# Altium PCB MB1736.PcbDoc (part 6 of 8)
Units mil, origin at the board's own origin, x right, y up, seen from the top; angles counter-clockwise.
Board outline 5905.51 x 3779.53 mil, 6 copper layers (Top Layer, L2_GND, L3_SIG, L4_VCC, L5_GND, Bottom Layer), stack 117.811 mil thick; 481 components, 387 nets, 1904 pads, 1200 vias.
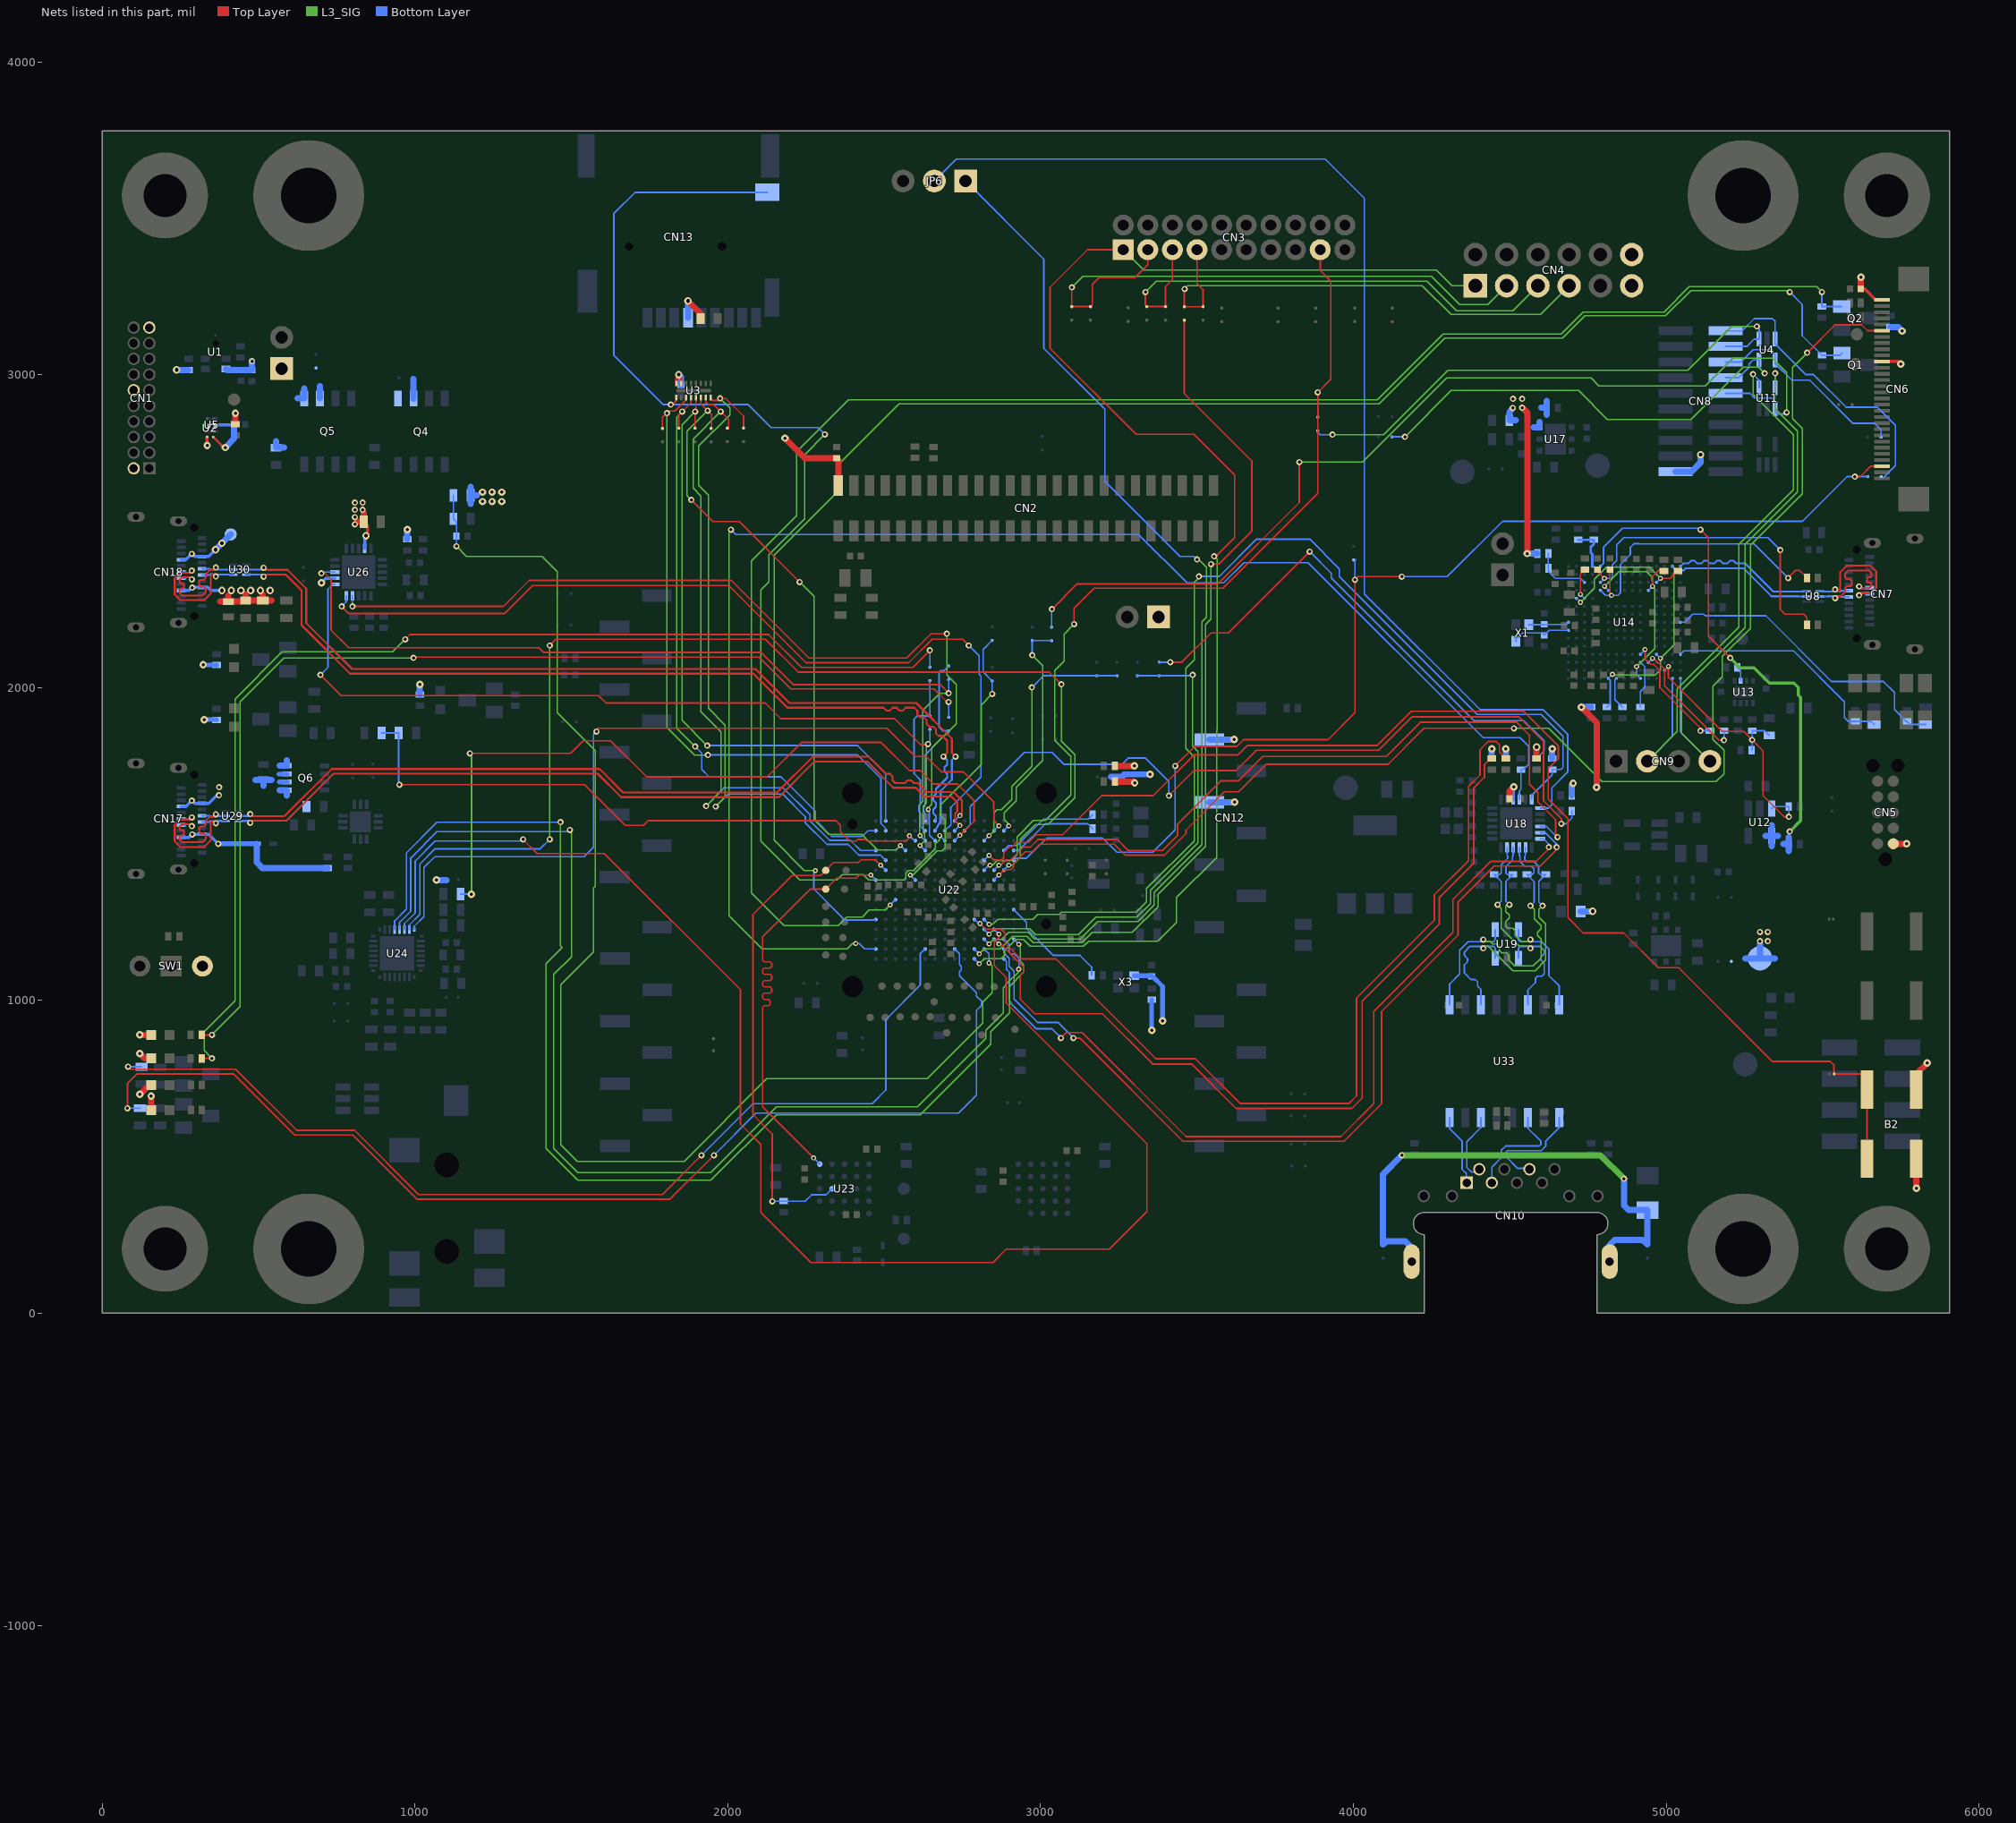
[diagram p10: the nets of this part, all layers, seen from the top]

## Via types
v1: diameter 20, hole 10, Top Layer to Bottom Layer, tented both sides, 518 vias
v2: diameter 16, hole 8, Top Layer to Bottom Layer, tented both sides, 311 vias
v3: diameter 24, hole 10, Top Layer to Bottom Layer, tented both sides, 301 vias
v4: diameter 24, hole 12, Top Layer to Bottom Layer, tented both sides, 61 vias
v5: diameter 23.62, hole 11.81, Top Layer to Bottom Layer, 9 vias

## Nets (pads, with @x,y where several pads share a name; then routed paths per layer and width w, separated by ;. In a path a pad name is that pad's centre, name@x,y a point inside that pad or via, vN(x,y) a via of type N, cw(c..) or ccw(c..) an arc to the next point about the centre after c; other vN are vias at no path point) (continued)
OCTOSPI_IO7: TP42.1 U22.G15 U23.E1 | length 1427
  Top Layer w5: 2252.5,1345.22 2111.09,1203.81 2111.09,1128.52 2116.09,1123.52 2135,1123.52 2140,1118.52 2140,1108.52 2135,1103.52 2116.09,1103.52 2111.09,1098.52 2111.09,1088.52 2116.09,1083.52 2135,1083.52 2140,1078.52 2140,1068.52 2135,1063.52 2116.09,1063.52 2111.09,1058.52 2111.09,1048.52 2116.09,1043.52 2135,1043.52 2140,1038.52 2140,1028.52 2135,1023.52 2116.09,1023.52 2111.09,1018.52 2111.09,1008.52 2116.09,1003.52 2130,1003.52 2135,998.52 2135,988.52 2130,983.52 2116.09,983.52 2111.09,978.52 2111.09,659.61 v2(2274.1,496.6) ; TP42.1@2312.76,1355.91 2347.76,1390.91 2409.69,1390.91 2419.76,1400.98 v2(2457.18,1400.98)
  Top Layer w5.22: 2252.5,1345.22 2263.19,1355.91 TP42.1@2312.76,1355.91
  Bottom Layer w5: v2(2274.1,496.6) U23.E1@2293.78,476.93 ; v2(2457.18,1400.98) U22.G15@2472.94,1385.25
OCTOSPI_NCS: R118.1 TP32.1 U22.F14 U23.C2 | length 1661.3
  Top Layer w5: v1(2141.81,358.19) 2141.81,573.18 2080.1,634.9 2080.1,1275.09 2205,1400 2296.85,1400 TP32.1@2312.76,1415.91 2337.76,1440.91 2417.25,1440.91 2426.34,1450 2471.14,1450 v2(2488.67,1432.47)
  Bottom Layer w5: v1(2141.81,358.19) 2177.32,358.19 R118.1@2177.76,358.62 2178.2,358.19 2247.19,358.19 ; v2(2488.67,1432.47) U22.F14@2504.4,1416.74
  Bottom Layer w5.22: 2247.19,358.19 2268,378.99 2313.96,378.99 U23.C2@2333.15,398.19
PA2: R92.1 U18.12 U22.L4 | length 3437.5
  L3_SIG w4: v2(2835.11,1243.5) 2846.81,1243.5 2863.3,1260 2975.01,1260 2990.01,1275 3060,1275 3067.01,1282 3306.07,1282 3339,1314.93 3339,1358 3491.5,1510.5 3491.5,1778.5 3464,1806 3464,2062 3491.5,2089.5 3491.5,2336.5 3506,2351 v1(3506,2356)
  Bottom Layer w4: U22.L4@2819.37,1259.25 v2(2835.11,1243.5)
  Bottom Layer w5: v1(3506,2356) 3571.01,2356 3689.99,2474.99 3860.01,2474.99 3955,2380 3955,2355 4395,1915 4600,1915 4670,1845 4670,1745 4663.39,1738.39 R92.1@4635.75,1738.4 4635.75,1722.05 4569.96,1656.25 4569.96,1648 U18.12@4569.99,1642.89
PA3: U22.N1 U24.28 | length 3898.2
  L3_SIG w4: v1(1465,1570) 1465,1175 1470,1170 1418.15,1118.15 1418.15,526.85 1520.01,424.99 1945,424.99 2155,635 2615,635 2840,860 2840,900 2900,960 2900,1045 2945,1090 2945,1115 2935,1125 2935,1174.59 v2(2930.3,1179.3)
  Bottom Layer w4: U22.N1@2913.89,1196.27 2930.3,1179.84 v2(2930.3,1179.3)
  Bottom Layer w5: U24.28@934.25,1226.57 934.25,1254.25 972,1292 972,1472 1070,1570 v1(1465,1570)
PA4: U22.M3 U24.30 | length 4726.4
  Top Layer w5: v1(1345,1515) 1390,1470 1605,1470 2040,1035 2040,605 2105,540 2105,322.49 2265,162.49 2847.5,162.49 2890,204.99 3220,204.99 3340,324.99 3340,542 2889.99,992.01 2889.99,1073.64 2852.11,1111.51 2852.11,1155.02 ; 2852.12,1155.03 2852.12,1186.51 2866.61,1201 v2(2866.61,1212.01)
  Bottom Layer w4: U22.M3@2850.87,1227.75 v2(2866.61,1212.01)
  Bottom Layer w5: U24.30@965.75,1226.57 965.75,1245.75 1000,1280 1000,1446 1064,1510 1340,1510 v1(1345,1515)
PA5: U22.N2 U24.29 | length 3812.3
  L3_SIG w4: v1(1495,1545) 1500,1540 1500,1140 1443.15,1083.15 1443.15,526.84 1520,449.99 1945,449.99 2155,660 2606.05,660 2825,878.94 2825,905 2880,960 2880,1040 2888,1048 2888,1049.98 2930,1091.98 v2(2930,1100)
  Bottom Layer w4: U22.N2@2882.39,1196.27 2891.31,1187.34 ; 2891.31,1187.32 2899.31,1179.32 2899.31,1154.8 2904.11,1150 2915,1150 2930,1135 v2(2930,1100)
  Bottom Layer w5: U24.29@950,1226.57 950,1250 986,1286 986,1456 1070,1540 1490,1540 v1(1495,1545)
PA7: SB20.2 SB47.2 U22.M4 | length 1573.9
  L3_SIG w4: v2(2835.11,1212.01) 2853.09,1230 2860.32,1230 2860.81,1229.5 2965.49,1229.5 2984,1211 3120.99,1211 3176,1266 3307.05,1266 3351,1309.95 3351,1352 3503.5,1504.5 3503.5,1796.5 3486,1814 v1(3486,2041)
  Bottom Layer w5: U22.M4@2819.38,1227.75 v2(2835.11,1212.01) ; SB47.2@3309.16,2038.31 3483.31,2038.31 v1(3486,2041)
PA15: SB53.2 SB72.2 U22.G11 | length 932.3
  L3_SIG w4: v2(2583.16,1400.98) 2590.98,1400.98 2668.91,1478.91 2684.76,1478.91 2694.76,1488.91 2694.76,1576.91 2678.76,1592.91 2678.76,1623.75 2810,1755 2810,1945 v1(2845,1980)
  Bottom Layer w5: v2(2583.16,1400.98) U22.G11@2598.88,1385.25 ; v1(2845,1980) SB53.2@2845,2021.37 2816,2050.38 2816,2122.38 SB72.2@2845,2151.37
PB0: U18.17 U22.P2 | length 2802.3
  Top Layer w5: v1(3105,880) 3125,880 3455,550 3970,550 4090,670 4090,965 4335,1210 4335,1315 4450,1430 4597.2,1430 4650,1482.8 v1(4650,1490)
  Bottom Layer w5: U22.P2@2882.39,1164.78 2882.38,1152.6 2899.5,1135.49 2899.5,1109.12 2915,1093.62 2915,1005 2990,930 3055,930 v1(3105,880) ; U18.17@4597.55,1536.59 4601.99,1536.58 4613.43,1536.57 4650,1500 v1(4650,1490)
PB1: U18.18 U22.R2 | length 2728.1
  Top Layer w5: v1(3065,880) 3082.5,897.5 3132.5,897.5 3465,565 3960,565 4065,670 4065,965 4318.3,1218.3 4318.3,1323.3 4440,1445 4585,1445 4625,1485 v1(4625,1490)
  Bottom Layer w5: U22.R2@2882.39,1133.28 2890.5,1125.16 2890.5,1099.5 2900,1090 2900,998.77 2905,993.77 2905,990 2985,910 3035,910 v1(3065,880) ; U18.18@4597.55,1516.9 4608.11,1516.89 4625,1500 v1(4625,1490)
PB2: JP6.1 U22.N4 | length 3351.4
  L3_SIG w4: v2(2835.12,1180.51) 2849.6,1195 2875,1195 2897.51,1217.5 2960.51,1217.5 2981.02,1197 3127,1197 3183.01,1253 3311.02,1253 3363,1304.98 3363,1346 3515.5,1498.5 3515.5,2210.5 3530,2225 3530,2385.94 3505.95,2410 v1(3500,2410)
  Bottom Layer w4: U22.N4@2819.38,1196.25 v2(2835.12,1180.51)
  Bottom Layer w5: JP6.1@2760,3620 3010,3370 3010,3085 3205,2890 3205,2660.5 3445.5,2420 3490,2420 v1(3500,2410)
PB3: SB31.2 SB68.2 U22.C4 | length 849.4
  L3_SIG w4: v2(2835.11,1526.95) 2850,1541.84 2850,1600 2860,1610 2875,1610 2908,1643 2908,1684.98 2972,1748.98 v1(2972,2001)
  Bottom Layer w4: U22.C4@2819.4,1511.24 v2(2835.11,1526.95)
  Bottom Layer w5: v1(2972,2001) 3009.31,2038.31 SB31.2@3179.16,2038.31 SB68.2@3244.16,2038.31
PB5: U22.B3 U24.32 | length 2633.7
  Top Layer w4: 2850,1612.12 2850,1575.09 v2(2866.62,1558.47)
  Top Layer w5: v1(1580,1860) 1580,1865 1585,1870 2508.77,1870 2598.77,1780 2633.65,1780 2682.65,1731 2753,1731 2850,1634 2850,1612.12
  Bottom Layer w4: U22.B3@2850.9,1542.73 v2(2866.62,1558.47)
  Bottom Layer w5: U24.32@997.24,1226.57 997.24,1237.24 1028,1268 1028,1425 1063,1460 1540,1460 1570,1490 1570,1850 v1(1580,1860)
PB10: R99.1 U18.10 U22.P15 | length 4841
  L3_SIG w4: v1(2010,2505) 2003.49,2498.49 2003.49,1271.5 2110,1165 2381.98,1165 2398.99,1182 v2(2409,1182)
  Bottom Layer w5: v1(2010,2505) 2025,2490 3313.01,2490 3468,2335 3585.01,2335 3650,2400 3855,2400 4415,1840 4532.58,1840 4560,1812.58 4560,1755 4543.38,1738.38 R99.1@4535.75,1738.4 4535.75,1675.35 4530.59,1670.19 U18.10@4530.59,1642.89 ; v2(2409,1182) 2419.78,1182 2437.01,1164.76 U22.P15@2472.94,1164.78
PC4: R47.1 U22.L5 | length 2894.1
  Top Layer w5: v2(2806.06,1245.94) 2824.01,1228 2873,1228 2886,1215 2886,1183 2936,1133 3049,1133 3368,814 3494,814 3637,671 3986,671 4010,695 4010,1008 4259,1257 4259,1338 4368,1447 4368,1684 4405,1721 4405,1802 4431,1828 4456,1828 4467,1817 4467,1794.4 R47.1@4487.56,1773.83
  Bottom Layer w4: U22.L5@2787.88,1259.25 2801.18,1245.94 v2(2806.06,1245.94)
PC5: R46.1 U22.N3 | length 2752.7
  Top Layer w5: v2(2866.62,1180.5) 2872.5,1180.5 2945,1108 2945,1090 2935,1080 2935,1004 2981.51,957.5 3197.51,957.5 3358,797 3483,797 3625,655 3995,655 4028,688 4028,998 4275,1245 4275,1330 4385,1440 4385,1680 4419,1714 4419,1754 4434,1769 4434,1773.82 R46.1@4442.56,1773.83
  Bottom Layer w4: U22.N3@2850.87,1196.25 v2(2866.62,1180.5)
PC8: SB13.2 U3.7 U22.D15 | length 2156.3
  Top Layer w5: U3.7@1929.36,2927.35 1929.36,2913.64 1938,2905 1955,2905 v1(1977,2883) 2002,2858 2002,2826.62
  L3_SIG w4: v1(1930,1622) 1978,1670 1978,1859 1914,1923 1914,2613 1889,2638 1889,2795 v1(1977,2883)
  Bottom Layer w5: v1(1930,1622) 1988,1680 2176,1680 2176.11,1680.11 2262.33,1593.9 2262.33,1574.67 2325,1512 2392,1512 2424.28,1479.72 U22.D15@2472.94,1479.74
PC9: SB15.2 U3.8 U22.E14 | length 2239.5
  Top Layer w5: U3.8@1945.12,2927.36 1945.12,2924.88 1952,2918 1968.01,2918 v1(1975,2925) 1993.01,2925 2050,2868 SB15.2@2050,2830
  L3_SIG w4: v1(1961,1620) 1991,1650 1991,1881 1938,1934 1938,2616 1907,2647 1907,2773 2006,2872 2006,2894 v1(1975,2925)
  Bottom Layer w5: v1(1961,1620) 2001,1660 2175.01,1660 2247.33,1587.67 2247.33,1568.89 ; 2247.32,1568.88 2317.19,1499 2384,1499 2418.28,1464.72 2487.92,1464.72 2494.82,1457.82 ; 2494.84,1457.82 U22.E14@2504.44,1448.24
PC10: SB10.2 U3.3 U22.B14 | length 2071.5
  Top Layer w4: SB10.2@1791,2829 1791,2864 v1(1805,2878) 1812,2885 1831,2885 1866.38,2920.38 U3.3@1866.38,2927.36
  L3_SIG w4: v1(1805,2878) 1805,1873 1893,1785 v1(1936,1785)
  Bottom Layer w5: v1(1936,1785) 2415,1785 2489.41,1710.59 2489.41,1565.59 2504.43,1550.58 U22.B14@2504.44,1542.73
PC11: SB3.2 U3.4 U22.B15 | length 1967.9
  Top Layer w5: SB3.2@1843,2829.62 1843,2872 v1(1854,2883) 1882.13,2911.13 U3.4@1882.13,2927.34
  L3_SIG w4: v1(1854,2883) 1836,2865 1836,1871 v1(1895,1812)
  Bottom Layer w5: v1(1895,1812) 1916,1791 1916,1739 1940,1715 2170,1715 2280,1605 2280,1577 2332,1525 2430,1525 2447.71,1542.72 U22.B15@2472.94,1542.73
PC12: SB11.2 U3.6 U22.D12 | length 2005.5
  Top Layer w4: v1(1935,2886) 1948,2873 SB11.2@1948,2833
  Top Layer w5: v1(1883,2600) 1952,2531 2036,2531 v1(2229,2338) ; U3.6@1913.62,2927.35 1913.62,2907.38 v1(1935,2886)
  L3_SIG w4: v1(1883,2600) 1869,2614 1869,2820 v1(1935,2886) ; v1(2229,2338) 2275,2292 2275,1578.95 2322.95,1531 2428.41,1531 2448.95,1510.45 2449.54,1510.45 2478.54,1481.45 2537.67,1481.45 v2(2551.67,1495.45)
  Bottom Layer w4: v2(2551.67,1495.45) U22.D12@2567.43,1479.74
PC13: B2.3 B2.4 U7.1 U22.E4 | length 4133.3
  Top Layer w5: v2(2835.11,1463.97) 2850.38,1448.69 2873.7,1448.69 2882,1457 2882,1473 2901,1492 2909.12,1492 2922.54,1505.42 2960.86,1505.42 2985.44,1530 3070,1530 3195,1655 3360,1655 3490.01,1785 3630.01,1785 3660,1815 4075,1815 4185,1925 4544.39,1925 4655,1814.39 4655,1813.33 4655.25,1813.08 4655.25,1773.5 4623,1741.25 4623,1644.58 4680,1587.58 4680,1587.5 4686,1581.5 4686,1265 4735,1216 4864,1216 4975,1105 5040,1105 5340,805 5525,805 5536.65,793.34 U7.1@5536.66,765 5630,765 5642.52,752.48 B2.4@5642.52,494.54
  Bottom Layer w4: U22.E4@2819.4,1448.24 v2(2835.11,1463.97)
PC14: R112.2 U22.D2 | length 331.4
  Bottom Layer w5: U22.D2@2882.39,1479.74 2898.11,1495.45 2924.46,1495.45 2939.64,1510.64 2939.64,1510.85 3008.63,1579.84 3152.19,1579.84 R112.2@3166.3,1593.93
PC15: R111.2 U22.D1 | length 294.2
  Bottom Layer w5: U22.D1@2913.89,1479.74 2929.72,1479.72 3014.85,1564.84 3150.69,1564.84 R111.2@3166.27,1549.26
PD2: SB17.2 U3.5 U22.A14 | length 1976.8
  Top Layer w5: SB17.2@1895,2829.62 v1(1895,2883) 1895,2891 1897.87,2893.87 U3.5@1897.87,2927.35
  L3_SIG w4: v1(1895,2883) 1852.84,2840.84 1852.84,1896.16 v1(1934,1815)
  Bottom Layer w5: v1(1934,1815) 2415,1815 2504.43,1725.57 U22.A14@2504.44,1574.23
PD4: R70.1 R113.2 U22.C11 | length 1989.4
  Top Layer w5: v1(950,1690) 1541.65,1690 1671.65,1560 1730,1560 1745,1575 2345,1575 2360,1560 2360,1540 2390,1510 2410,1510 2415,1515 2440,1515 2445,1510 2570,1510 2580.66,1520.66 v2(2580.66,1526.57)
  Bottom Layer w4: v2(2580.66,1526.57) 2596,1511.23 U22.C11@2598.93,1511.24
  Bottom Layer w5: R70.1@892.56,1855 R113.2@947.44,1855 947.44,1692.56 v1(950,1690)
PD7: R89.1 U22.B6 | length 2577.6
  Top Layer w5: v1(3410,1655) 3490,1735 3625,1735 3690,1800 4081.22,1800 4188.22,1907 4529,1907 4608.25,1827.75 4608.25,1749.91 4608,1749.66 4608,1638.35 4665,1581.35 v1(4665,1565)
  Bottom Layer w5: U22.B6@2756.39,1542.73 2775,1561.34 2775,1620 2948.18,1793.17 3036.83,1793.17 3075.01,1755 3260,1755 3280,1775 3335,1775 3410,1700 v1(3410,1655) ; v1(4665,1565) 4680,1565 4698.47,1583.47 4698.47,1596 R89.1@4698.49,1606.09
PE2: SB49.2 SB73.2 U22.B2 | length 747.1
  L3_SIG w4: v2(2898.11,1558.45) 2898.11,1564.88 2884,1578.99 2884,1599.99 2922,1637.99 2922,1681.99 3007,1766.99 3007,2070 v1(2973,2104)
  Bottom Layer w4: U22.B2@2882.39,1542.73 v2(2898.11,1558.45)
  Bottom Layer w5: v1(2973,2104) SB49.2@2973,2150.38 SB73.2@3035,2150.38
PE5: CN3.9 SB76.2 U22.F4 | length 2875.2
  Top Layer w5: v1(3106.81,2203.18) 3106.81,2253.81 3171,2318 3583.01,2318 3886,2621 v1(3886,2944) 3928,2986 3928,3300 3893.96,3334.04 CN3.9@3893.96,3400.25
  L3_SIG w4: v2(2838,1432.47) 2846.81,1432.47 2860.81,1446.47 2904.47,1446.47 2925,1467 2925,1523 2977,1575 3015,1575 3097,1657 3097,1780 3045,1832 3045,2055 3075,2085 3075,2171.38 v1(3106.81,2203.18)
  Bottom Layer w4: U22.F4@2819.4,1416.75 2835.11,1432.47 v2(2838,1432.47)
  Bottom Layer w5: SB76.2@3886,2864.8 v1(3886,2944)
PE6: CN6.3 SB51.1 SB77.2 U22.E1 | length 3811.7
  Top Layer w5: v1(3430,1750) 3492.5,1812.5 3627.5,1812.5 3649,1834 3919,1834 4005,1920 v1(4005,2345) 4015,2355 v1(4155,2355) ; v1(5603,2675) 5621.32,2675 5654.5,2708.18 CN6.3@5690,2708.18
  Bottom Layer w5: U22.E1@2913.89,1448.24 2920.63,1455 2955,1455 3020,1520 3197.46,1520 3243.45,1474 3358.33,1474 3430,1545.67 v1(3430,1750) ; v1(4005,2345) 4005,2406 4008,2409 ; v1(4155,2355) 4300,2355 4476.9,2531.9 5435.9,2531.9 5579,2675 v1(5603,2675) SB77.2@5644.69,2675
PE9: SB7.1 U22.P5 | length 2775.6
  Top Layer w5: SB7.1@3459.31,3174.75 3459.31,2940.68 3675,2725 3675,2500.25 3569.75,2395 v1(3545,2395)
  L3_SIG w4: v2(2803.62,1149.01) 2819.6,1165 2870.91,1165 2910.91,1205 2956.04,1205 2976.04,1185 3131.98,1185 3164.98,1218 3293,1218 3375,1300 3375,1340 3527.5,1492.5 3527.5,2202.5 3545,2220 v1(3545,2395)
  Bottom Layer w5: U22.P5@2787.9,1164.74 v2(2803.62,1149.01)
PE10: CN3.1 CN4.1 U22.R5 | length 4662.1
  Top Layer w5: CN3.1@3264.04,3400.25 3150.26,3400.25 3030,3280 3030,3085 3305,2810 3489.64,2810 3620,2679.64 3620,2480 3560,2420 v1(3555,2420)
  L3_SIG w4: v2(2803.62,1117.52) 2820.09,1134 2874,1134 2885,1145 2885,1160 2920,1195 2945,1195 2967,1173 3136.96,1173 3153.96,1190 3374.06,1190 3434.01,1249.94 3434.01,1329 3562.5,1457.49 3562.5,1863.43 3564,1864.93 3564,2411 v1(3555,2420) ; CN3.1@3264.04,3400.25 3329.3,3335 4265,3335 4315,3285 CN4.1@4390,3285
  Bottom Layer w5: U22.R5@2787.9,1133.25 v2(2803.62,1117.52)
PF5: CN6.25 U22.G3 | length 4452.3
  Top Layer w5: v2(2866.61,1400.98) 2883.6,1417.97 2904.12,1417.97 2912.61,1426.45 2912.61,1437.6 2950.42,1475.42 2973.3,1475.42 2997.88,1500 3235,1500 3270,1465 3396.22,1465 3465,1533.77 3465,1545 3587.5,1667.5 3632.5,1667.5 3720,1755 4110,1755 4225,1870 v1(4513,1870) ; v1(5451.01,3071) 5540,3160 5625,3160 5643.74,3141.25 CN6.25@5690,3141.25
  L3_SIG w4: v1(4513,1870) 4625,1870 4795,1700 5160,1700 5185,1725 5185,1800 5150,1835 5150,2005 5180,2035 5180,2100 5270,2190 5270,2455 5435,2620 5435,2829 5404,2860 5404,3024 v1(5451.01,3071)
  Bottom Layer w4: U22.G3@2850.9,1385.25 v2(2866.61,1400.98)
PF14: C136.2 R135.2 R136.1 U22.P4 | length 4264.8
  L3_SIG w4: v1(1132.28,2452.27) 1164.56,2420 1405,2420 1454,2371 1454,1921 1576,1799 1576,1364.94 1570,1358.94 1570,1155 1466,1051 1466,537.94 1517.95,486 1859.95,486 2123.95,750 2637,750 2815,928 2815,995 2845,1025 2845,1110 v2(2835,1120)
  Bottom Layer w5: R136.1@1122.44,2615 R135.2@1122.44,2540 1132.29,2530.15 1132.29,2485 v1(1132.28,2452.27) ; U22.P4@2819.4,1164.78 2835,1149.17 v2(2835,1120)
PG11: U18.16 U22.F3 | length 2406.6
  Top Layer w5: v2(2866.61,1432.47) 2872.47,1432.47 2889.47,1449.47 2904.12,1449.47 2945.07,1490.42 2967.08,1490.42 2991.66,1515 3245,1515 3280,1480 3390,1480 3437.5,1527.5 3437.5,1562.5 3577.5,1702.5 3632.5,1702.5 3710,1780 4105,1780 4215,1890 4521.01,1890 4563,1848 4563,1691 4590,1664 4590,1635.14 4646.5,1578.64 4646.5,1528.25 v1(4652.38,1522.38)
  Bottom Layer w4: U22.F3@2850.9,1416.75 v2(2866.61,1432.47)
  Bottom Layer w5: U18.16@4597.55,1556.27 4617.05,1556.26 4650.94,1522.38 v1(4652.38,1522.38)
PG12: U22.F2 U24.31 | length 3731.8
  Top Layer w5: v1(1430,2135) 1450,2155 2120,2155 2225,2050 3027.01,2050 v1(3066,2011)
  L3_SIG w4: v1(1430,1515) v1(1430,2135) ; v2(2898.11,1432.47) 2909.47,1432.47 2935,1458 2935,1515 2983,1563 3023,1563 3109,1649 3109,1786 3065,1830 3066,1831 v1(3066,2011)
  Bottom Layer w4: U22.F2@2882.39,1416.75 v2(2898.11,1432.47)
  Bottom Layer w5: U24.31@981.5,1226.57 981.5,1241.5 1015,1275 1015,1436 1064,1485 1400,1485 v1(1430,1515)
PH0: R114.2 U22.K1 | length 363.3
  Bottom Layer w5: U22.K1@2913.87,1290.75 2955,1249.62 2955,1230 3041,1144 3126,1144 3163.16,1106.84 R114.2@3163.18,1080.51
PM0: SB45.1 U22.D10 U26.1 | length 2758.3
  Top Layer w5: v1(697,2041) 763,1975 1586,1975 1610,1951 2119,1951 2169,1901 2533,1901 2615.87,1818.12 2638.13,1818.12 v1(2640,1820)
  L3_SIG w4: v2(2614.66,1495.45) 2628.66,1509.45 2628.66,1532.75 2625,1536.42 2625,1621.15 2635,1631.15 2635,1815 v1(2640,1820)
  Bottom Layer w4: v2(2614.66,1495.45) 2622.56,1487.56 U22.D10@2630.42,1479.74
  Bottom Layer w5: v1(697,2041) 721,2065 721,2316 735.35,2330.34 U26.1@743.36,2330.35 ; v1(2640,1820) 2645.87,1825.86 SB45.1@2645.87,1866.16
PM1: SB43.1 U22.C10 U26.3 | length 2882.2
  Top Layer w5: v1(700,2366) 711,2366 731,2346 731,2184 787.5,2127.5 1395.5,2127.5 1410,2113 2105.42,2113 2208.42,2010 2678.46,2010 v1(2705.87,1982.59)
  L3_SIG w4: v2(2614.66,1526.95) 2612.9,1528.72 2612.9,1626.34 2623,1636.44 2623,1696.75 2622.5,1697.25 2622.5,1927.5 2677.59,1982.59 v1(2705.87,1982.59)
  Bottom Layer w4: v2(2614.66,1526.95) U22.C10@2630.39,1511.23
  Bottom Layer w5: v1(700,2366) 703.71,2369.7 U26.3@743.36,2369.73 ; v1(2705.87,1982.59) SB43.1@2705.87,2026.15
PM2: SB45.2 SB46.2 U22.B10 | length 543.7
  Bottom Layer w5: U22.B10@2630.42,1542.73 2619.08,1554.06 2615,1558.11 2615,1600 2610,1605 2610,1622.75 2615,1627.75 2615,1705.4 2595,1725.4 2595,1900 2604.44,1909.44 2645.87,1909.44 SB46.2@2645.87,2022.22
PM3: SB42.2 SB43.2 U22.A10 | length 594.9
  Bottom Layer w5: U22.A10@2630.42,1574.23 2630.42,1600.5 2625,1605.92 2625,1616.52 2630,1621.52 2630,1785 2695.87,1850.86 2700.87,1850.86 2705.87,1855.86 SB42.2@2705.87,1862.22 ; 2687.79,1862.2 SB42.2@2705.87,1862.22 ; SB43.2@2705.87,2069.44 2690.87,2054.44 2679.45,2054.44 2675,2050 2675,1875 2687.78,1862.22 SB42.2@2705.87,1862.22
PM5: U22.B9 U30.5 | length 2873.6
  Top Layer w6.1: v1(515.24,2383.25) 521.74,2376.75 591.92,2376.75 651.76,2316.91 651.76,2206.45 798.22,2060 2087.66,2060 2196.66,1951 2602.22,1951 2715.99,1837.23 2715.99,1791.67 v1(2727.66,1780)
  Bottom Layer w6.1: U30.5@459.67,2377.5 485.45,2377.5 485.82,2377.12 509.12,2377.12 v1(515.24,2383.25) ; U22.B9@2661.92,1542.73 2680.45,1576 2680.45,1670.44 2715.99,1705.99 2715.99,1768.33 v1(2727.66,1780)
PM6: U22.A9 U30.6 | length 2872.5
  Top Layer w6.1: v1(515.24,2355.25) 521.74,2361.75 585.7,2361.75 636.76,2310.68 636.76,2200.24 792,2045 2081.44,2045 2190.44,1936 2497.6,1936 2506.4,1927.19 2518.4,1927.19 2527.2,1936 2539.2,1936 2548,1927.19 2560,1927.19 2568.8,1936 2596,1936 2606.03,1925.97 2606.03,1913.51 2614.52,1905.02 2626.97,1905.02 2635.45,1896.55 2635.45,1884.09 2643.94,1875.6 2656.39,1875.6 2664.87,1867.12 2664.87,1854.67 2673.36,1846.18 2685.81,1846.18 2700.99,1831 2700.99,1791.66 v1(2689.33,1780)
  Bottom Layer w6.1: U30.6@459.67,2361.75 485.44,2361.75 485.82,2362.12 508.36,2362.12 v1(515.24,2355.25) ; U22.A9@2661.92,1574.23 2665.45,1577.76 2665.45,1589.76 2656.65,1598.57 2656.65,1610.57 2665.45,1619.36 2665.45,1631.36 2656.65,1640.17 2656.65,1652.17 2665.45,1660.97 2665.45,1676.67 2700.99,1712.2 2700.99,1724.2 2692.19,1733 2692.19,1745 2700.99,1753.81 2700.99,1768.34 v1(2689.33,1780)
PM8: U22.C9 U26.19 | length 2823.2
  Top Layer w5: v1(799.44,2260) 1282,2260 1365,2343 2011,2343 2259,2095 2572,2095 2649.5,2172.5 v1(2700,2172.5)
  L3_SIG w4: v2(2640.73,1610.72) 2641.6,1611.59 2641.6,1616.59 2651.76,1626.75 2651.76,1806.91 2730,1885.15 2730,2010 2700,2040 v1(2700,2172.5)
  Bottom Layer w4: v2(2640.73,1610.72) 2640.73,1609.26 2645,1605 2645,1528.1 2654.05,1519.06 U22.C9@2661.9,1511.23
  Bottom Layer w5: v1(799.44,2260) U26.19@799.46,2293.94
PM9: U22.B8 U26.20 | length 2889.8
  Top Layer w5: v1(765,2260) 788,2237 1286,2237 1376,2327 2003,2327 2250,2080 2578,2080 2653,2155 2750,2155 v1(2770,2135)
  Bottom Layer w4: U22.B8@2693.39,1542.72 2712.5,1561.83 2712.5,1582.5
  Bottom Layer w5: v1(765,2260) 779.76,2274.75 U26.20@779.77,2293.94 ; 2712.5,1582.5 2712.5,1617.5 2809,1714 2809,2037 2803,2043 2803,2102 v1(2770,2135)
PM11: U22.B7 U29.6 | length 2603.8
  Top Layer w6.1: v1(472.24,1568.25) 478.74,1574.75 588.76,1574.75 738.95,1724.94 1583.83,1724.94 1658.78,1650 2163.22,1650 2277.22,1764 2444.78,1764 2528.78,1680 2600.78,1680 2628.78,1652 2714.78,1652 2733.05,1633.73 2733.05,1603.66 2726.58,1597.18 2726.58,1574.5 v2(2741.63,1559.45)
  Bottom Layer w6.1: U29.6@435.67,1574.25 466.25,1574.25 v1(472.24,1568.25) ; U22.B7@2724.89,1542.72 v2(2741.63,1559.45)
PM12: U22.A7 U29.5 | length 2605.7
  Top Layer w6.1: v1(472.24,1596.25) 478.74,1589.75 582.54,1589.75 732.78,1740 1590,1740 1665,1665 2157,1665 2271,1779 2451,1779 2505.58,1724.42 2518.03,1724.42 2526.52,1715.93 2526.52,1703.48 2535,1695 2565.4,1695 2574.2,1703.8 2586.2,1703.8 2595,1695 2607,1695 2635,1667 2721,1667 2748.05,1639.94 2748.05,1597.43 2741.63,1591.01 v2(2741.63,1590.94)
  Bottom Layer w6.1: U29.5@435.67,1590 465.98,1590 v1(472.24,1596.25) ; U22.A7@2724.91,1574.23 v2(2741.63,1590.94)
PM13: R131.2 U22.C7 | length 2440
  Top Layer w5: v1(1175,1790) 1497.44,1790 1537.44,1830 1625,1830 1740,1715 2125.01,1715 2235,1825 2490.11,1825 2580.11,1735 2614.99,1735 2657.99,1692 2734,1692 2787.1,1638.9 2787.1,1573.42 v2(2741.63,1527.95)
  L3_SIG w5: v1(1175,1790) 1174.21,1789.21 1180,1783.43 v3(1180,1340)
  Bottom Layer w5: R131.2@1145.12,1340 v3(1180,1340) ; U22.C7@2724.89,1511.22 v2(2741.63,1527.95)
PM14: CN13.10 U3.1 U22.C8 | length 3914.7
  Top Layer w5: v1(1817,2905) 1822,2905 1834.88,2917.88 U3.1@1834.88,2927.35
  L3_SIG w4: v1(2310,2810) 2245,2745 2245,2540 2131,2426 2131,2338 2105,2312 2105,1510 2230,1385 2347.98,1385 2364.98,1402 2433,1402 2450,1385 2562.85,1385 2569.16,1391.31 2569.16,1406.77 2577.36,1414.98 2592.83,1414.98 2663.63,1485.77 2663.63,1501.3 2677.14,1514.81 v2(2677.14,1527.47)
  Bottom Layer w4: v2(2677.14,1527.47) U22.C8@2693.37,1511.24
  Bottom Layer w5: CN13.10@2102,3583.77 1703.78,3583.77 1635,3515 1635,3063 1793,2905 v1(1817,2905) 2065,2905 2138,2832 2288,2832 v1(2310,2810) ; CN13.10@2102.01,3583.78 CN13.10@2126.27,3583.8
PMOD2: CN3.2 CN4.2 SB1.2 SB2.2 | length 1913.3
  Top Layer w5: v1(3100,3280) 3099.31,3279.31 SB1.2@3099.31,3218.37 3159.3,3218.34 3165,3224.05 3165,3289 3187,3311 3301,3311 3342.78,3352.77 CN3.2@3342.78,3400.25
  L3_SIG w4: v1(3100,3280) 3135,3315 4250,3315 4340,3225 4430,3225 CN4.2@4490,3285
PMOD3: CN3.3 CN4.3 SB5.2 SB6.2 | length 1641.6
  Top Layer w5: v1(3335,3265) 3335,3222.66 3339.31,3218.34 3345.99,3218.35 3399.31,3218.35 3399.31,3282.31 3421.52,3304.51 CN3.3@3421.52,3400.25
  L3_SIG w4: v1(3335,3265) 3370,3300 4235,3300 4330,3205 4510,3205 CN4.3@4590,3285
PMOD4: CN3.4 CN4.4 SB7.2 SB8.2 | length 1618
  Top Layer w5: v1(3460,3275) 3459.31,3274.31 SB7.2@3459.31,3218.06 SB8.2@3518.99,3218.03 ; CN3.4@3500.26,3400.25 3500.26,3291.74 3519.31,3272.68 SB8.2@3519.31,3218.37 ; SB8.2@3518.99,3218.03 SB8.2@3519.31,3218.35 ; SB8.2@3519,3218.03 SB8.2@3519.31,3218.34
  L3_SIG w4: v1(3460,3275) 3470,3285 4220,3285 4312,3193 4598,3193 CN4.4@4690,3285
PN7: Q2.2 R65.1 U22.J13 | length 5621.1
  L3_SIG w4: v2(2518.84,1305.17) 2502.68,1289 2451.38,1289 2429.37,1267 2380,1267 2353,1240 2180,1240 2075.49,1344.5 2075.49,2405.49 2220,2550 2220,2755 2385,2920 4077,2920 4287,3130 4663.8,3130 4734.8,3201 4992.98,3201 5073.98,3282 5480.95,3282 v1(5497.95,3265)
  Bottom Layer w4: v2(2518.84,1305.17) U22.J13@2535.93,1322.25
  Bottom Layer w5: v1(5497.95,3265) R65.1@5497.95,3218.91 5498.27,3218.59 Q2.2@5561.37,3218.6
PN12: Q1.2 R64.1 U22.L15 | length 5346.9
  L3_SIG w4: v2(2280,1415.5) 2244.5,1415.5 2148,1512 2148,2423.64 2358,2633.64 2358,2718.62 2547.37,2908 4081.98,2908 4291.98,3118 4668.78,3118 4739.78,3189 4997.96,3189 5078.96,3270 5391,3270 5395,3266 v1(5395,3265)
  Bottom Layer w5: v2(2280,1415.5) 2280,1415 2275,1410 2275,1356.2 2374.08,1257.12 2440.87,1257.12 2441,1257 2470.67,1257 U22.L15@2472.94,1259.27 ; v1(5395,3265) 5435,3225 5435,3125.73 R64.1@5498,3062.73 5555.29,3062.73 Q1.2@5562.19,3069.62
PO1: R171.1 U22.P7 | length 3664.6
  Top Layer w5: v1(80,655.7) 80,735 110,765 420,765 615,570 800,570 1005,364.99 1815,364.99 v1(1955,505)
  Bottom Layer w5: v1(80,655.7) 113,655.7 R171.1@120,655.72 ; v1(1955,505) 2090,640 2738,640 2795,697 2795,968.3 2811.36,984.66 2811.36,997.51 2795,1013.88 2795,1025 2740.63,1079.36 2740.63,1092.51 2745.8,1097.68 2745.8,1109.7 2740.63,1114.88 2740.63,1149.01 U22.P7@2724.9,1164.75
PO5: R170.1 U22.P10 | length 3276.7
  Top Layer w5: v1(81.73,788.26) 90,780 426.22,780 621.22,585 806.22,585 1011.22,379.99 1790,379.99 v1(1915,505)
  Bottom Layer w5: v1(81.73,788.26) R170.1@125,788.28 ; v1(1915,505) 2080,670 2461,670 2505,714 2505,939 2615,1049 2615,1149.35 U22.P10@2630.42,1164.78
RD_N: R100.1 U18.22 U19.6 U33.8 | length 763.4
  L3_SIG w4.1: v1(4499.12,1306) 4491.6,1306 4487.5,1301.9 4487.5,1284.38 4498.3,1273.58 4498.3,1263.58 4487.5,1252.77 4487.5,1237.5 4494.57,1230.42 4509.85,1230.42 4516.92,1223.35 4516.92,1208.08 4536.76,1188.24 4559.86,1188.24 v1(4566.36,1194.74)
  Bottom Layer w5.1: v1(4499.12,1306) 4487.5,1317.61 4487.5,1380.24 R100.1@4510,1402.73 4492.58,1402.74 4487.5,1407.82 4487.5,1427.5 4508.56,1448.56 4508.56,1461.43 4510.91,1463.78 4510.91,1474 U18.22@4510.93,1489.34 ; U19.6@4528.19,1226.01 4528.18,1193.34 4533.28,1188.24 4559.86,1188.24 v1(4566.36,1194.74) 4572.86,1188.24 4601.75,1188.24 4625,1164.99 4625,1080 4657.76,1047.24 U33.8@4657.76,986.02
RD_P: R103.1 U18.23 U19.1 U33.6 | length 765.5
  L3_SIG w4.1: v1(4460.88,1306) 4472.5,1294.38 4472.5,1231.27 4530.54,1173.24 4559.86,1173.24 v1(4566.36,1166.74)
  Bottom Layer w5.1: v1(4460.88,1306) 4472.5,1317.61 4472.5,1380.24 R103.1@4450,1402.73 4467.42,1402.74 4472.5,1407.82 4472.5,1433.72 4493.56,1454.77 4493.56,1461.43 4491.22,1463.77 4491.22,1475 U18.23@4491.25,1489.34 ; U19.1@4528.19,1135.45 4528.18,1168.14 4533.28,1173.24 4559.86,1173.24 v1(4566.36,1166.74) 4572.86,1173.24 4595.53,1173.24 4610,1158.76 4610,1148.76 4600.2,1138.97 4600.2,1128.97 4610,1119.17 4610,1085 4602.93,1077.92 4589.06,1077.92 4581.99,1070.85 4581.99,1056.99 4557.76,1032.75 U33.6@4557.76,986.02
RMII.RMII_CRS_DV: R96.1 SB20.1 | length 1703.2
  Top Layer w5: v1(3414.84,2081.62) 3451.63,2081.62 3545,2175 3600,2175 v1(3860,2435)
  Bottom Layer w5: SB20.1@3379.16,2081.62 v1(3414.84,2081.62) ; v1(3860,2435) 3929,2366 3929,2351 4385,1895 4545,1895 4610,1830 4610,1798.09 4605.25,1793.34 4605.25,1792.67 4593.83,1781.25 4593.16,1781.25 R96.1@4585.75,1773.83
RMII.RMII_MDC: JP6.2 U18.13 | length 3844.2
  Bottom Layer w5: JP6.2@2660,3620 2730,3690 3910,3690 4035,3565 4035,2300 4405,1930 4606.22,1930 4685,1851.22 4685,1730 4634.4,1679.4 4634.4,1625.9 4623.81,1615.31 4618,1615.31 U18.13@4597.55,1615.33
RX_N: CN10.6 U33.9 | length 349.5
  Bottom Layer w5.1: CN10.6@4563,463 4525.67,463 4487.76,500.91 4487.76,514.9 4492.86,520 4600.87,520 4614.76,533.89 4614.76,549.75 4657.76,592.75 U33.9@4657.76,625.78
RX_P: CN10.3 U33.11 | length 351.9
  Bottom Layer w5.1: CN10.3@4442.52,419.69 4442.52,467.5 4472.76,497.75 4472.76,521.11 4486.64,535 4594.65,535 4599.76,540.1 4599.76,550.23 4557.76,592.23 U33.11@4557.76,625.78
SHGND: C158.1 CN10.SH1 CN10.SH2 SB69.1 SB70.1 | length 1658.9
  L3_SIG w20: v1(4155,505) 4790,505 v1(4865,429.99)
  Bottom Layer w20: v1(4155,505) 4095,444.99 SB70.1@4095,219.68 4105.32,229.99 4166.22,229.99 4186.22,209.99 CN10.SH1@4186.22,167.72 ; CN10.SH2@4819.29,167.72 4819.29,219.28 4835,234.99 4924.68,234.99 SB69.1@4940,219.68 C158.1@4940,329.88 4880.12,329.88 4865,344.99 v1(4865,429.99)
STLK_LED: R62.2 R63.2 U14.D15 | length 750.4
  Bottom Layer w5: U14.D15@5045.77,2106.67 5056.58,2117.5 5407.5,2117.5 5570,1955 5570,1905 5582.72,1892.27 R63.2@5605,1892.29 5655.16,1892.27 R62.2@5665,1882.45
STLK_OSC_IN: C95.2 U14.G1 X1.1 | length 191.6
  Bottom Layer w5: X1.1@4519.33,2148.43 4519.33,2153.47 4540.77,2174.91 4602.82,2174.91 C95.2@4610,2167.72 4625.72,2183.44 U14.G1@4687.5,2183.44
STLK_OSC_OUT: C96.1 U14.H1 X1.3 | length 129.9
  Bottom Layer w5: X1.3@4560.67,2201.57 4609.29,2201.58 C96.1@4610,2202.29 4680.75,2202.28 U14.H1@4687.5,2209.03
STLK_SWCLK: CN9.2 U11.4 U14.A14 | length 1833.9
  L3_SIG w4: CN9.2@4940,1765 5035,1860 5035,1996.22 5232.76,2193.98 5232.76,2458.98 5406.89,2633.1 5406.89,2808.1 5277.5,2937.5 v1(5277.5,3002.5)
  Bottom Layer w4: 5020.17,2010.91 U14.A14@5020.18,2029.9
  Bottom Layer w5: CN9.2@4940,1765 5020.17,1845.17 5020.17,2010.91 ; v1(5277.5,3002.5) 5297.17,2982.83 U11.4@5297.17,2959.36
STLK_SWDIO: CN9.4 U11.5 U14.A15 | length 1809.8
  L3_SIG w4: CN9.4@5140,1765 5050,1855 5050,1990 5252.76,2192.75 5252.76,2457.75 5420,2625 5420,2820 5348.35,2891.65 v1(5348.35,3005)
  Bottom Layer w4: 5045.76,2010.91 U14.A15@5045.77,2029.9
  Bottom Layer w5: 5045.76,2010.91 5045.76,2005 5045.75,1859.25 CN9.4@5140,1765 ; U11.5@5348.35,2959.36 v1(5348.35,3005)
STLK_UCPD_CC1_C: C61.1 R53.1 U14.M5 | length 952
  Top Layer w4: C61.1@4820,2377.29 4820,2300 v2(4825,2295)
  Top Layer w5: v1(5390,2350.91) 5414.09,2375 5425.95,2375 5430.55,2370.4 5431.08,2370.4 5442.5,2358.98 5442.5,2358.44 R53.1@5450.04,2350.91
  Bottom Layer w4: U14.M5@4789.86,2311.4 4806.24,2295 v2(4825,2295)
  Bottom Layer w5: v2(4825,2295) 4845.75,2295 4854,2303.25 4854,2394 4885.55,2425.55 4885.55,2448.69 4896.97,2460.11 4913.13,2460.11 4913.25,2460 5280.91,2460 v1(5390,2350.91)
STLK_UCPD_CC2_C: C59.1 R54.1 U14.N5 | length 1050.1
  Top Layer w5: C59.1@4780,2377.29 4780,2372.41 v2(4802.65,2349.75) ; v1(5365,2440) 5365,2250 5380,2235 5440,2235 5450.04,2224.95 R54.1@5450.04,2200.91
  Bottom Layer w5: U14.N5@4789.86,2336.99 v2(4802.65,2349.75) 4824.76,2349.75 4827.37,2352.35 4827.37,2392.35 4842,2407 4842,2457 4865,2480 5325,2480 v1(5365,2440)
STLK_USB_CN_N: CN7.A7 CN7.B7 U8.2 | length 465.2
  Top Layer w6.1: v1(5540.01,2286) 5546.51,2292.5 5558.51,2292.5 5571.77,2305.76 5571.77,2317.98 5578.77,2324.98 5588.77,2324.98 5593.77,2329.98 5593.77,2340.98 5587.77,2346.98 5578.77,2346.98 5571.77,2353.98 5571.77,2363.76 5583.01,2375 5647.76,2375 5656.77,2365.98 5656.77,2356.98 5652.77,2352.98 5645.77,2352.98 5641.77,2348.98 5641.77,2339.98 5645.77,2335.98 5652.77,2335.98 5656.77,2331.98 5656.77,2325.5 5648.61,2317.34 5623.44,2317.34 v1(5616.94,2323.84)
  Bottom Layer w6.1: U8.2@5490.67,2292 5516.45,2292 5516.82,2292.36 5533.64,2292.36 v1(5540.01,2286) 5546.51,2292.5 5557.87,2292.5 5560.21,2290.16 CN7.A7@5584.02,2290.16 ; v1(5616.94,2323.84) 5623.45,2317.33 5635.56,2317.33 5637.92,2319.68 CN7.B7@5650.93,2319.67
STLK_USB_CN_P: CN7.A6 CN7.B6 U8.1 | length 465
  Top Layer w6.1: v1(5540.01,2314) 5546.51,2307.5 5552.28,2307.5 5556.77,2311.98 5556.77,2369.98 5576.78,2390 5653.98,2390 5671.77,2372.2 5671.77,2319.27 5654.83,2302.34 5623.44,2302.34 v1(5616.94,2295.84)
  Bottom Layer w6.1: U8.1@5490.67,2307.74 5516.44,2307.75 5516.82,2307.36 5533.38,2307.36 v1(5540.01,2314) 5546.51,2307.5 5557.87,2307.5 5560.21,2309.84 CN7.A6@5584.02,2309.84 ; v1(5616.94,2295.84) 5623.43,2302.33 5637.68,2302.33 5640.01,2300 CN7.B6@5650.93,2299.99
STLK_USB_N: U8.5 U14.R14 | length 474.6
  Bottom Layer w6.1: U14.R14@5020.15,2388.15 5033,2375.3 5056.3,2375.3 5063,2382 5246.78,2382 5336.41,2292.36 5423.18,2292.36 5423.55,2292 U8.5@5449.33,2292
STLK_USB_P: U8.6 U14.R15 | length 473.7
  Bottom Layer w6.1: U14.R15@5045.77,2388.17 5054.59,2397 5070.2,2397 5079,2405.8 5091,2405.8 5099.8,2397 5111.8,2397 5120.6,2405.8 5132.6,2405.8 5141.4,2397 5153.4,2397 5162.2,2405.8 5174.2,2405.8 5183,2397 5195,2397 5203.8,2405.8 5215.8,2405.8 5224.6,2397 5253,2397 5342.63,2307.36 5423.18,2307.36 5423.56,2307.75 U8.6@5449.33,2307.74
STLK_VCP_RX: R52.1 U14.C10 | length 154.2
  Bottom Layer w5: R52.1@4917.76,1938.62 4917.76,1987.75 4931.98,2001.97 4931.98,2066.92 U14.C10@4917.82,2081.08
STLK_VCP_TX: R56.1 U14.A7 | length 104.4
  Bottom Layer w5: U14.A7@4841.04,2029.9 4835.83,2024.69 4835.83,1961.89 R56.1@4860,1937.72
T_JTDI: R49.1 U14.L3 | length 102.6
  Top Layer w5: v2(4725.91,2298.61) 4725.91,2363.19 R49.1@4740,2377.29
  Bottom Layer w5: v2(4725.91,2298.61) U14.L3@4738.68,2285.81
T_PWR_EN: R66.2 R177.2 U12.4 U13.2 U14.R5 | length 1842.3
  Top Layer w5: v1(5110,2505) 5135,2480 5135,2165 v1(5205,2095)
  L3_SIG w10: v1(5205,2095) 5236,2064 5281,2064 5330,2015 5408,2015 5423,2000 5423,1975.88 5430,1968.88 5430,1575 v1(5395,1540)
  Bottom Layer w5: U14.R5@4789.85,2388.16 4800,2398.31 4800,2450 4860,2510 5105,2510 v1(5110,2505) ; v1(5205,2095) 5227.72,2072.27 R177.2@5227.72,2065 5238.2,2054.51 U13.2@5238.2,2022.09
  Bottom Layer w20: 5317.59,1526.69 U12.4@5337.42,1526.69 ; 5337.42,1493.09 U12.4@5337.42,1526.69 ; 5337.42,1560.31 U12.4@5337.42,1526.69 ; 5357.25,1526.69 U12.4@5337.42,1526.69 ; 5374.23,1500 R66.2@5392.3,1500 ; 5392.29,1478.19 R66.2@5392.3,1500 ; 5392.29,1521.8 R66.2@5392.3,1500
T_PWR_EXT: R86.1 R88.1 U14.R4 | length 141
  Bottom Layer w8: R88.1@4719.18,2472.82 R86.1@4769.18,2472.82 4769.18,2459.84 4759,2449.66 4759,2432.25 4764.27,2426.99 U14.R4@4764.27,2388.17
T_PWR_INT: C4.2 R67.1 R68.2 R75.2 U12.3 U14.B13 | length 921.7
  Top Layer w5: v2(5007.39,2068.27) 5007.39,2032.6 5180,1860 5248.15,1860 v1(5275,1833.15) 5310,1798.15 5310,1655 5377.71,1587.28 v1(5392.29,1587.28)
  Bottom Layer w5: U14.B13@4994.61,2055.5 v2(5007.39,2068.27) ; R67.1@5272.73,1800 5275,1802.26 v1(5275,1833.15) R75.2@5275,1862.29 5315.15,1862.28 C4.2@5330,1847.43 ; U12.3@5337.42,1613.31 5344.11,1620 R68.2@5392.3,1620 v1(5392.29,1587.28)
T_PWR_LED: R59.2 R60.2 U14.H15 | length 973.3
  Bottom Layer w5: U14.H15@5045.77,2209.03 5059.03,2209.02 5085,2235 5120,2235 5125,2230 5318.83,2230 5528.83,2020 5695,2020 5730,1985 5730,1930 5767.72,1892.27 R60.2@5770,1892.29 5779.84,1882.43 R59.2@5830,1882.45
T_PWR_SEL1: R80.2 U14.D10 | length 390.2
  Top Layer w5: v2(4932.4,2121.85) 4932.4,2092.59 4950,2075 4959.99,2075 4980,2054.99 4980,2000 5110,1870 v1(5110,1862.27)
  Bottom Layer w5: U14.D10@4917.8,2106.67 4932.4,2121.26 v2(4932.4,2121.85) ; v1(5110,1862.27) R80.2@5140,1862.29
T_PWR_SEL2: R77.2 U14.C11 | length 417.2
  Top Layer w5: v2(4956.2,2093.85) 4961.14,2093.85 4995,2060 4995,2006.22 5169.22,1832 v1(5185,1832)
  Bottom Layer w5: U14.C11@4943.41,2081.08 v2(4956.2,2093.85) ; v1(5185,1832) R77.2@5185,1862.29
T_SWCLK: R73.1 U14.A10 U14.M6 U14.M11 | length 654.3
  Top Layer w4: 4952.76,2351.92 4952.76,2342.59 4956.17,2339.17 v2(4956.17,2324.17)
  Top Layer w5: 4952.76,2351.92 4979.02,2378.18 4987.76,2378.18 R73.1@4992.76,2373.19
  L3_SIG w4: v2(4802.67,2324.18) 4849.39,2370.91 4937.76,2370.91 4956.17,2352.5 v2(4956.17,2324.17) 4963.76,2316.59 4963.76,2124.91 4906.48,2067.62 v2(4905.48,2067.62)
  Bottom Layer w4: v2(4905.48,2067.62) 4905.76,2067.34 4905.76,2041.95 U14.A10@4917.82,2029.9 ; U14.M11@4943.39,2311.4 v2(4956.17,2324.17)
  Bottom Layer w5: v2(4802.67,2324.18) U14.M6@4815.45,2311.4
T_SWDIO: R74.1 U14.L2 U14.N12 | length 437.9
  Top Layer w5: v2(4981.76,2349.76) 5014.34,2349.76 5019.38,2354.81 5019.38,2358.55 5034.02,2373.18 R74.1@5037.76,2373.19
  L3_SIG w4: v2(4725.86,2273) 4753.75,2300.91 4770.76,2317.92 4770.76,2346.91 4808.76,2384.91 4946.62,2384.91 v2(4981.76,2349.76)
  Bottom Layer w4: U14.N12@4969,2336.99 v2(4981.76,2349.76)
  Bottom Layer w5: U14.L2@4713.09,2285.81 v2(4725.86,2273)
T_SWO: R51.1 U14.A6 U14.D12 | length 618.7
  L3_SIG w4: v2(4828.27,2042.67) 4830.95,2040 4965,2040 4981.76,2056.75 v2(4981.76,2093.85) 5025,2137.09 5025,2360.92
  Bottom Layer w5: R51.1@4810,1937.72 4820.83,1948.55 4820.83,2024.52 U14.A6@4815.45,2029.9 v2(4828.27,2042.67) v2(4828.27,2042.67) ; U14.D12@4968.98,2106.64 v2(4981.76,2093.85)
T_VCC: B2.1 B2.2 C1.2 C2.2 C3.2 C13.2 C15.1 C50.2 C76.2 C97.1 C107.1 C125.2 CN1.2 CN1.12 CN1.19 CN2.50 CN4.6 CN4.12 CN5.1 CN6.20 CN6.30 CN8.1 CN12.2 CN12.4 CN13.4 JP5.1 L1.2 LD1.1 LD2.1 LD3.1 LD4.1 R7.1 R8.1 R9.2 R44.1 R45.1 R48.2 R61.2 R90.2 R91.1 R92.2 R94.2 R102.2 R104.2 R110.1 R150.2 R166.1 R167.1 SB21.2 SB30.1 SB57.1 SW1.2 TP3.1 U1.5 U2.4 U2.5 U3.15 U3.16 U5.5 U17.6 U18.9 U26.2 X3.4 | length 3999.4
  Top Layer w8: U2.5@354.45,2801.34 387.77,2768 v3(393,2768) ; U3.16@1834.88,2972.63 1834.88,2993.02 v4(1842.76,3000.91) 1850.63,2993.03 U3.15@1850.63,2972.63
  Top Layer w10: U2.4@334.76,2801.34 334.76,2774.76 v3(335,2775) ; C76.2@5622.74,3275 5635,3275 5670.31,3239.68 CN6.30@5690,3239.68 ; CN6.20@5690,3042.84 5742.16,3042.84 v3(5750,3035)
  Top Layer w20: v3(120,700) 150,730 LD2.1@155.97,730 ; v3(120,830) 135,815 LD3.1@155.5,815 ; v3(120,890) LD4.1@155.5,890 ; LD1.1@155.97,650 155.95,668.99 v3(155.94,694.06) ; R7.1@425,2842.72 v3(425,2878) ; v4(1872.33,3236.34) 1912.44,3196.23 C13.2@1912.44,3180 ; v3(2183,2798) 2183,2797 2246.5,2733.5 C15.1@2347.87,2733.52 2352.88,2728.5 CN2.50@2352.88,2646.31 ; R44.1@3237.74,1700 3296,1700 v3(3300.5,1695.5) ; R45.1@3237.74,1750 v3(3300,1750) ; C50.2@4499.09,1644.84 4499.09,1669.09 v3(4512.5,1682.5) ; v1(4540,2895) 4556.1,2878.9 v3(4556.1,2428.95) ; R48.2@4585.75,1773.83 v4(4585.75,1810) ; v3(4728.82,1937.72) 4778,1888.54 v3(4778,1682) ; C76.2@5622.74,3275 v3(5622.72,3312.27) ; CN5.1@5726.3,1501.22 v3(5768.78,1501.22) ; v3(5800,399.99) B2.2@5800,494.54 ; B2.1@5800,715.01 5800,765 v3(5835,800)
  Bottom Layer w10: U5.5@361.81,2840 419.28,2840 C1.2@421.28,2842 ; v3(700,2335) 715.03,2350.02 U26.2@743.36,2350.04
  Bottom Layer w12: U18.9@4510.93,1642.89 4510.91,1680.91 v3(4512.5,1682.5)
  Bottom Layer w15: v3(322,2073) 364.28,2073 R167.1@365,2072.29 ; v3(326,1898) 364.28,1898 R166.1@365,1897.29 ; X3.4@3298.7,1079.12 3353.15,1079.12 C107.1@3355,1077.29 3357.73,1077.27 3390,1045 v3(3390,935) ; v3(3355,905) R110.1@3355,1002.29
  Bottom Layer w20: v4(237.35,3015.99) R8.1@275,3015.99 ; v3(393,2768) 421.28,2796.28 C1.2@421.28,2842 ; U1.5@394.98,3019.07 397.97,3016.08 C3.2@442.55,3016.07 477.65,3016.07 C2.2@478,3015.72 v1(478,3044) ; R150.2@1015,1977.73 v3(1015,2010) ; v3(1067.72,1385) SB57.1@1100,1385 ; v4(1842.76,3000.91) 1850,2993.67 C125.2@1850,2967.73 ; CN13.4@1872.33,3182.22 v4(1872.33,3236.34) ; SB30.1@3224.69,1715 3260,1715 3268,1723 v3(3350,1723) ; CN12.4@3539,1634.25 v3(3620,1634.25) ; CN12.2@3539,1834.25 3564,1834.25 v3(3619.25,1834.25) ; R104.2@4442.56,1773.83 v3(4442.56,1805) ; R102.2@4487.56,1773.83 v3(4487.56,1805) ; v1(4509.6,2894.3) 4498.59,2880.32 C97.1@4498.6,2854.77 4519.21,2854.77 ; v3(4556.1,2428.95) R94.2@4587.6,2428.95 ; 4577,2832.19 U17.6@4594.86,2832.2 4594.86,2849.08 ; 4600.26,2894.77 R91.1@4618.33,2894.77 ; 4618.32,2872.98 R91.1@4618.33,2894.77 ; 4618.32,2916.58 R91.1@4618.33,2894.77 ; R92.2@4635.75,1773.83 v3(4635.75,1805) ; R90.2@4698.49,1656.09 4698.48,1689.98 v3(4702.5,1694) ; L1.2@4726.5,1285 v4(4765,1285) ; v3(4728.82,1937.72) R9.2@4760,1937.72 ; CN8.1@5029.89,2691 5081.01,2691 5110,2719.99 v4(5110,2745) ; 5252.61,1135 TP3.1@5300,1135 ; v1@5300,1182.39 TP3.1@5300,1135 ; 5347.39,1135 TP3.1@5300,1135 ; R61.2@5717,3153.02 5742,3153 v3(5755,3140)
  other v1: 5300,1190 5325,1190 5300,1219 5325,1219 4539.5,2923.4 4510,2923.8
T_VCC_AIN: R93.1 R94.1 U14.N3 | length 187.1
  Bottom Layer w5: R94.1@4623.04,2428.95 R93.1@4623.04,2381.7 4623.03,2371.97 4645.21,2349.78 4725.88,2349.78 U14.N3@4738.68,2336.99
TD_N: R95.1 U18.20 U19.3 U33.3 | length 1043.1
  L3_SIG w4.1: v1(4415.2,1166.73) 4421.7,1173.23 4431.77,1173.23 4510,1095 4581.22,1095 4615,1128.77 4615,1245 4593,1267 4593,1291.38 v1(4604.62,1303)
  Bottom Layer w5.1: U33.3@4407.76,986.02 4407.76,1035.24 4396.97,1046.02 4396.97,1059.9 4389.9,1066.97 4376.03,1066.97 4355,1088 4355,1114.17 4364.8,1123.97 4364.8,1133.97 4355,1143.76 4355,1155 4373.22,1173.23 4408.7,1173.23 v1(4415.2,1166.73) 4421.7,1173.23 4448.28,1173.23 4453.38,1168.12 U19.3@4453.38,1135.45 ; U18.20@4550.28,1478 4550.28,1463.78 4547.93,1461.43 4547.93,1450.09 4553.03,1445 4575.3,1445 4592.4,1427.9 4592.4,1406.98 4596.64,1402.74 R95.1@4615,1402.73 4593,1380.74 4593,1314.61 v1(4604.62,1303) ; U18.20@4550.29,1478 U18.20@4550.3,1489.34
TD_P: R98.1 U18.21 U19.4 U33.1 | length 1044.6
  L3_SIG w4.1: v1(4415.2,1194.73) 4421.7,1188.23 4437.99,1188.23 4445.06,1181.16 4460.34,1181.16 4467.41,1174.09 4467.41,1158.81 4474.48,1151.74 4489.76,1151.74 4496.83,1144.67 4496.83,1129.39 4516.22,1110 4575,1110 4600,1135 4600,1197.17 4589.2,1207.98 4589.2,1217.98 4600,1228.77 4600,1238.77 4578,1260.77 4578,1291.38 v1(4566.38,1303)
  Bottom Layer w5.1: U33.1@4307.76,986.02 4307.76,1052.75 4340,1085 4340,1161.23 4367,1188.23 4408.7,1188.23 v1(4415.2,1194.73) 4421.7,1188.23 4448.28,1188.23 4453.38,1193.33 U19.4@4453.38,1226.01 ; U18.21@4530.6,1489.34 4530.6,1477 4530.59,1463.77 4532.93,1461.43 4532.93,1443.88 4546.81,1430 4569.08,1430 4577.4,1421.67 4577.4,1408.32 4571.82,1402.74 R98.1@4555,1402.73 4578,1379.74 4578,1314.61 v1(4566.38,1303)
TRACE_CLK: CN8.12 SB73.1 U11.1 | length 3226.7
  Top Layer w5: v1(3036,2251) 3117,2332 3567.01,2332 3827,2592 v1(3827,2721)
  L3_SIG w4: v1(3827,2721) 4029,2721 4298,2990 4759.99,2990 4784.99,2965 5125,2965 5214,3054 5339,3054 5385,3008 v1(5385,2880)
  Bottom Layer w5: SB73.1@3035,2193.68 3035,2250 v1(3036,2251) ; CN8.12@5190.13,2941 5267.67,2941 5282.76,2925.91 5337.76,2925.91 5348.35,2915.32 5348.35,2881.64 5354.99,2875 5380,2875 v1(5385,2880)
TRACE_D0: CN8.14 SB74.1 U4.5 | length 1554.7
  L3_SIG w4: v1(4165,2802) 4313,2950 4720,2950 4812,2858 5079.99,2858 5246.98,3025 5295,3025 v1(5315,3005)
  Bottom Layer w5: SB74.1@4123.31,2802 v1(4165,2802) ; CN8.14@5190.13,2991 5231,2991 5265,3025 5265,3035 5277.44,3047.43 U4.5@5297.17,3047.44 5297.17,3022.83 v1(5315,3005)
TRACE_D1: CN8.16 SB75.1 U4.4 | length 660.2
  Bottom Layer w5: CN8.16@5190.13,3041 5237.85,3041 5277.76,3080.91 5332.76,3080.91 5348.35,3065.32 5348.35,3036.65 5402,2983 5459,2983 5597,2845 5667,2845 5687,2825 SB75.1@5687,2801
TRACE_D2: CN8.18 SB76.1 U4.1 | length 1717.4
  L3_SIG w4: v1(3933,2809) 4096,2809 4302,3015 5070,3015 5210,3155 v1(5290,3155)
  Bottom Layer w5: 3885,2815 3886,2816 ; SB76.1@3886,2821.49 3886,2816 ; v1(3933,2809) 3893,2809 3886,2816 ; CN8.18@5190.13,3091 5257.85,3091 5281.22,3114.36 U4.1@5297.17,3114.36 5297.17,3147.83 v1(5290,3155)
TRACE_D3: CN8.20 SB77.1 U4.3 | length 925.2
  Bottom Layer w5: CN8.20@5190.13,3141 5242.85,3141 5281.85,3180 5340,3180 5348.35,3171.65 U4.3@5348.35,3114.36 5348.35,3099.65 5447,3001 5471,3001 5575,2897 5675,2897 5733,2839 5733,2710 5695,2672
TX_N: CN10.2 U33.14 | length 228.4
  Bottom Layer w5.1: CN10.2@4402.37,463 4401.19,461.72 4392.22,452.03 4378.56,451.52 4362.76,466.17 4362.76,548.91 4407.76,593.91 U33.14@4407.76,625.78
TX_P: CN10.1 U33.16 | length 228.5
  Bottom Layer w5.1: U33.16@4307.76,625.78 4307.76,589.91 4347.76,549.91 4347.76,459.61 4361.17,447.18 CN10.1@4362.21,419.69
UCPD_SNK: Q4.5 Q4.6 SB61.2 | length 62.4
  Bottom Layer w20: Q4.6@995,2924.6 995,2987
UCPD_SOURCE1: C157.1 CN19.1 Q5.5 Q5.6 SB64.2 | length 138.4
  Bottom Layer w20: 555,2788.18 C157.1@555,2767.57 580.54,2767.57 ; 624.18,2924.92 Q5.5@645,2924.92 645,2957.56 ; Q5.6@695,2924.92 695,2963.67
USB1_CN_HS_N: CN18.A7 CN18.B7 U30.2 | length 471.6
  Top Layer w6.1: v1(285.83,2346.16) 279.33,2352.66 254.16,2352.66 246,2344.5 246,2338.01 250,2334.01 257,2334.01 261,2330.01 261,2321.01 257,2317.01 250,2317.01 246,2313.01 246,2304.01 255.01,2295 319.76,2295 331,2306.23 331,2316.01 324,2323.01 315,2323.01 309,2329.01 309,2340.01 314,2345.01 324,2345.01 331,2352.01 331,2364.23 344.26,2377.5 356.26,2377.5 v1(362.76,2384)
  Bottom Layer w6.1: CN18.B7@251.82,2350.31 265.08,2350.32 267.43,2352.67 279.32,2352.67 v1(285.83,2346.16) ; CN18.A7@318.75,2379.84 342.56,2379.84 344.9,2377.5 356.27,2377.5 v1(362.76,2384) 369.64,2377.11 392.18,2377.11 392.56,2377.5 U30.2@418.33,2377.5
USB1_CN_HS_P: CN18.A6 CN18.B6 U30.1 | length 471
  Top Layer w6.1: v1(285.83,2374.16) 279.33,2367.66 247.94,2367.66 231,2350.72 231,2297.79 248.8,2280 325.99,2280 346,2300.01 346,2358.01 350.49,2362.5 356.26,2362.5 v1(362.76,2356)
  Bottom Layer w6.1: CN18.B6@251.82,2369.99 262.76,2370 265.09,2367.67 279.34,2367.67 v1(285.83,2374.16) ; CN18.A6@318.75,2360.15 342.55,2360.16 344.9,2362.5 356.25,2362.5 v1(362.76,2356) 368.88,2362.11 392.18,2362.11 392.55,2361.75 U30.1@418.33,2361.75
USB2_CN_FS_N: CN17.A7 CN17.B7 U29.2 | length 446.7
  Top Layer w6.1: v1(285.83,1557.15) 279.33,1563.65 254.16,1563.65 246,1555.49 246,1549 250,1545 257,1545 261,1541 261,1532 257,1528 250,1528 246,1524 246,1515 255.01,1505.99 319.76,1505.99 331,1517.22 331,1527 324,1534 315,1534 309,1540 309,1551 314,1556 324,1556 331,1563 331,1575.22 344.26,1588.49 356.26,1588.49 v1(362.76,1594.99)
  Bottom Layer w6.1: CN17.B7@251.82,1561.3 265.08,1561.31 267.43,1563.66 279.32,1563.66 v1(285.83,1557.15) ; CN17.A7@318.75,1590.83 342.55,1590.84 344.9,1588.49 356.26,1588.49 v1(362.76,1594.99) 367.75,1590 U29.2@394.33,1590
USB2_CN_FS_P: CN17.A6 CN17.B6 U29.1 | length 447.4
  Top Layer w6.1: v1(285.83,1585.15) 279.33,1578.65 247.94,1578.65 231,1561.7 231,1508.78 248.8,1490.99 325.99,1490.99 346,1511 346,1569 350.49,1573.49 356.26,1573.49 v1(362.76,1566.99)
  Bottom Layer w6.1: CN17.B6@251.82,1580.99 262.75,1581 265.09,1578.66 279.34,1578.66 v1(285.83,1585.15) ; CN17.A6@318.75,1571.15 342.56,1571.15 344.9,1573.49 356.26,1573.49 v1(362.76,1566.99) 370.02,1574.25 U29.1@394.33,1574.25
USER_LED.LED3: R3.1 SB46.1 | length 3660.2
  Top Layer w5: R3.1@317.74,815 v1(350,815) ; v1(968,2155) 983,2170 2130,2170 2235,2065 2591.19,2065 v1(2645.87,2119.67)
  L3_SIG w4: v1(350,815) 325,840 325,900 424,999 424,1964 575,2115 928,2115 v1(968,2155)
  Bottom Layer w5: SB46.1@2645.87,2065.53 v1(2645.87,2119.67)
USER_LED.LED4: R4.1 SB42.1 | length 3567.9
  Top Layer w5: R4.1@317.74,890 v1(350,890) ; v1(995,2095.5) 997.5,2098 2099.2,2098 2201.19,1996 2659,1996 2700.87,1954.12 v1(2705.87,1954.12)
  L3_SIG w4: v1(350,890) 440,980 440,1955 580.5,2095.5 v1(995,2095.5)
  Bottom Layer w5: SB42.1@2705.87,1905.53 v1(2705.87,1954.12)
VBUS1: C156.2 CN18.A4 CN18.A9 CN18.B4 CN18.B9 R134.2 R136.2 R151.1 R163.1 TP43.1 U26.9 U31.1 | length 829
  Top Layer w10: R134.2@835.2,2530.91 847.76,2518.34 847.76,2490.91 v4(842.76,2485.91)
  Top Layer w20: 377.02,2275.51 U31.1@402.76,2275.51 ; 402.76,2294.36 U31.1@402.76,2275.51 ; 457.76,2299.09 C156.2@457.76,2278.46 ; 483.3,2278.47 C156.2@457.76,2278.46 ; 485.05,2278.47 R163.1@512.76,2278.46 ; 512.76,2299.09 R163.1@512.76,2278.46 ; 540.47,2278.47 R163.1@512.76,2278.46 ; 814.58,2530.91 R134.2@835.2,2530.91 835.2,2558.61 ; U31.1@402.76,2275.51 454.81,2275.51 C156.2@457.76,2278.46
  Bottom Layer w10: CN18.B9@251.82,2310.94 276.93,2310.94 v1@286,2320 ; CN18.B4@251.82,2409.36 267.14,2409.37 v1(286,2428.23) 295.02,2419.21 339.98,2419.21 ; v1@287.78,2320.78 CN18.A4@318.75,2320.78 336.97,2320.78 346.76,2311 v4(382,2311) ; CN18.A9@318.75,2419.21 339.98,2419.22 ; v4(361.76,2441) 339.98,2419.22 ; U26.9@838.83,2445.51 838.82,2481.97 v4(842.76,2485.91)
  Bottom Layer w20: v4(361.76,2441) 361.76,2441.76 v4(382,2462) TP43.1@410,2490 ; R151.1@975,2474.62 v3(975,2505) ; 1177.56,2587.28 R136.2@1177.56,2615 ; 1177.56,2642.7 R136.2@1177.56,2615 ; 1198.18,2615 R136.2@1177.56,2615
  other v1: 287,2320 807,2522 807,2545 807,2569 832,2569 807,2592 832,2592
  other v3: 1215,2595 1246,2595 1277.01,2595 1215,2625 1246,2625 1277,2625
  other v4: 412,2311 442.76,2310.91 474,2311 505,2311 536.24,2311.09
VBUS2: C5.1 CN17.A4 CN17.A9 CN17.B4 CN17.B9 D7.1 Q6.5 Q6.6 Q6.7 Q6.8 R159.2 U32.1 | length 882.3
  Bottom Layer w10: CN17.B9@251.82,1521.93 276.93,1521.93 286,1531 v1(287,1531) 287.78,1531.78 CN17.A4@318.75,1531.78 339.9,1531.77 v1(370.46,1501.22) ; CN17.B4@251.82,1620.36 267.14,1620.36 v1(286,1639.23) 295.02,1630.2 339.98,1630.2 361.76,1651.99
  Bottom Layer w15: v1(370.46,1501.22) D7.1@493.44,1501.22 ; 564.65,1724.01 Q6.7@589.96,1724.01 ; 565.28,1698.42 Q6.6@589.96,1698.42
  Bottom Layer w20: 489.26,1705.41 U32.1@515,1705.41 ; D7.1@493.44,1501.22 493.43,1441.57 511.51,1423.49 R159.2@720,1423.52 ; 515,1686.56 U32.1@515,1705.41 ; 540.74,1705.41 U32.1@515,1705.41 ; 567.17,1671.84 Q6.5@589.96,1671.84 589.96,1654.97 ; 567.17,1750.59 Q6.8@589.96,1750.59 589.96,1767.47
  other v1: 372.76,1655.91 373,1682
